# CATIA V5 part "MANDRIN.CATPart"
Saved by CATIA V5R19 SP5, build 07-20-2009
Part number: MANDRIN
Bounding box of the stored display mesh (mm): x -105 to 105, y -105 to 105, z 0 to 90
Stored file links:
  C:\Users\Laurent\Desktop\Sujet National E33\CFAO Catia\MANDRIN.CATPart
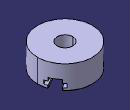
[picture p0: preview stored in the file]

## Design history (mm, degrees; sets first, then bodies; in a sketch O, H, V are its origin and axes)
Body1 (main body)
  Sketch1 on xy-plane, origin (0, 0, 0), H (1, 0, 0), V (0, 1, 0)
    circle A1 centre (0, 0) radius 105
    radius A1 = 105
  Pad1: profile Sketch1, direction (0, 0, 1), length 90
  Sketch2 on end face of Pad1, origin (0, 0, 90), H (1, 0, 0), V (0, 1, 0)
    circle A1 centre (0, 0) radius 30
    radius A1 = 30
  Pocket1: profile Sketch2, direction (0, 0, -1), through (limit type 3)
  Sketch3 on zx-plane, origin (0, 0, 0), H (-1, 0, 0), V (0, 0, 1)
    line L1 (-20, -2) -> (-20, 11)
    line L2 (-20, 11) -> (-32.5, 11)
    line L3 (-32.5, 11) -> (-32.5, 25)
    line L4 (-32.5, 25) -> (-20, 25)
    point P5 (-20, 25)
    line L5 (-20, 25) -> (-20, 38)
    line L6 (-20, 38) -> (20, 38)
    line L7 (20, 38) -> (20, 25)
    point P8 (20, 25)
    line L8 (20, 25) -> (32.5, 25)
    line L9 (32.5, 25) -> (32.5, 11)
    point P10 (32.5, 11)
    line L10 (32.5, 11) -> (20, 11)
    point P11 (20, 11)
    line L11 (20, 11) -> (20, -2)
    line L12 (20, -2) -> (-20, -2)
    reference projected line E1 (-105, 0) -> (105, 0) from edge [start face of Pad1 | face of Pad1 from Sketch1.A1]
    length L12 = 40
    distance L5 L3 = 12.5
    length L10 = 12.5
    distance L1 V = 20
    distance L6 L12 = 40
    length L1 = 13
    length L3 = 14
    distance L12 E1 = 2
    vertical: L1 V, L3 V, L5 V, L7 V, L9 V, L11 V
    horizontal: L2 H, L4 H, L6 H, L8 H, L10 H, L12 H
    coincidence: P5 L1, P8 L4, P10 L2, P11 L7
  Pocket2: profile Sketch3, direction (0, -1, 0), length 150
  CircPattern1: of Pocket2, instances 3, angular step 120, axis from face of Pad1 from Sketch1.A1
  Fillet1: radius 2, on edge [start face of Pad1 | face of Pad1 from Sketch1.A1] (x3)
  Chamfer1: length 1, angle 45, on edge [face of Pocket2 from Sketch3.L1 | start face of Pad1]; edge [face of CircPattern1 | start face of Pad1] (x2); edge [start face of Pad1 | face of CircPattern1] (x2); edge [start face of Pad1 | face of Pocket2 from Sketch3.L11]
